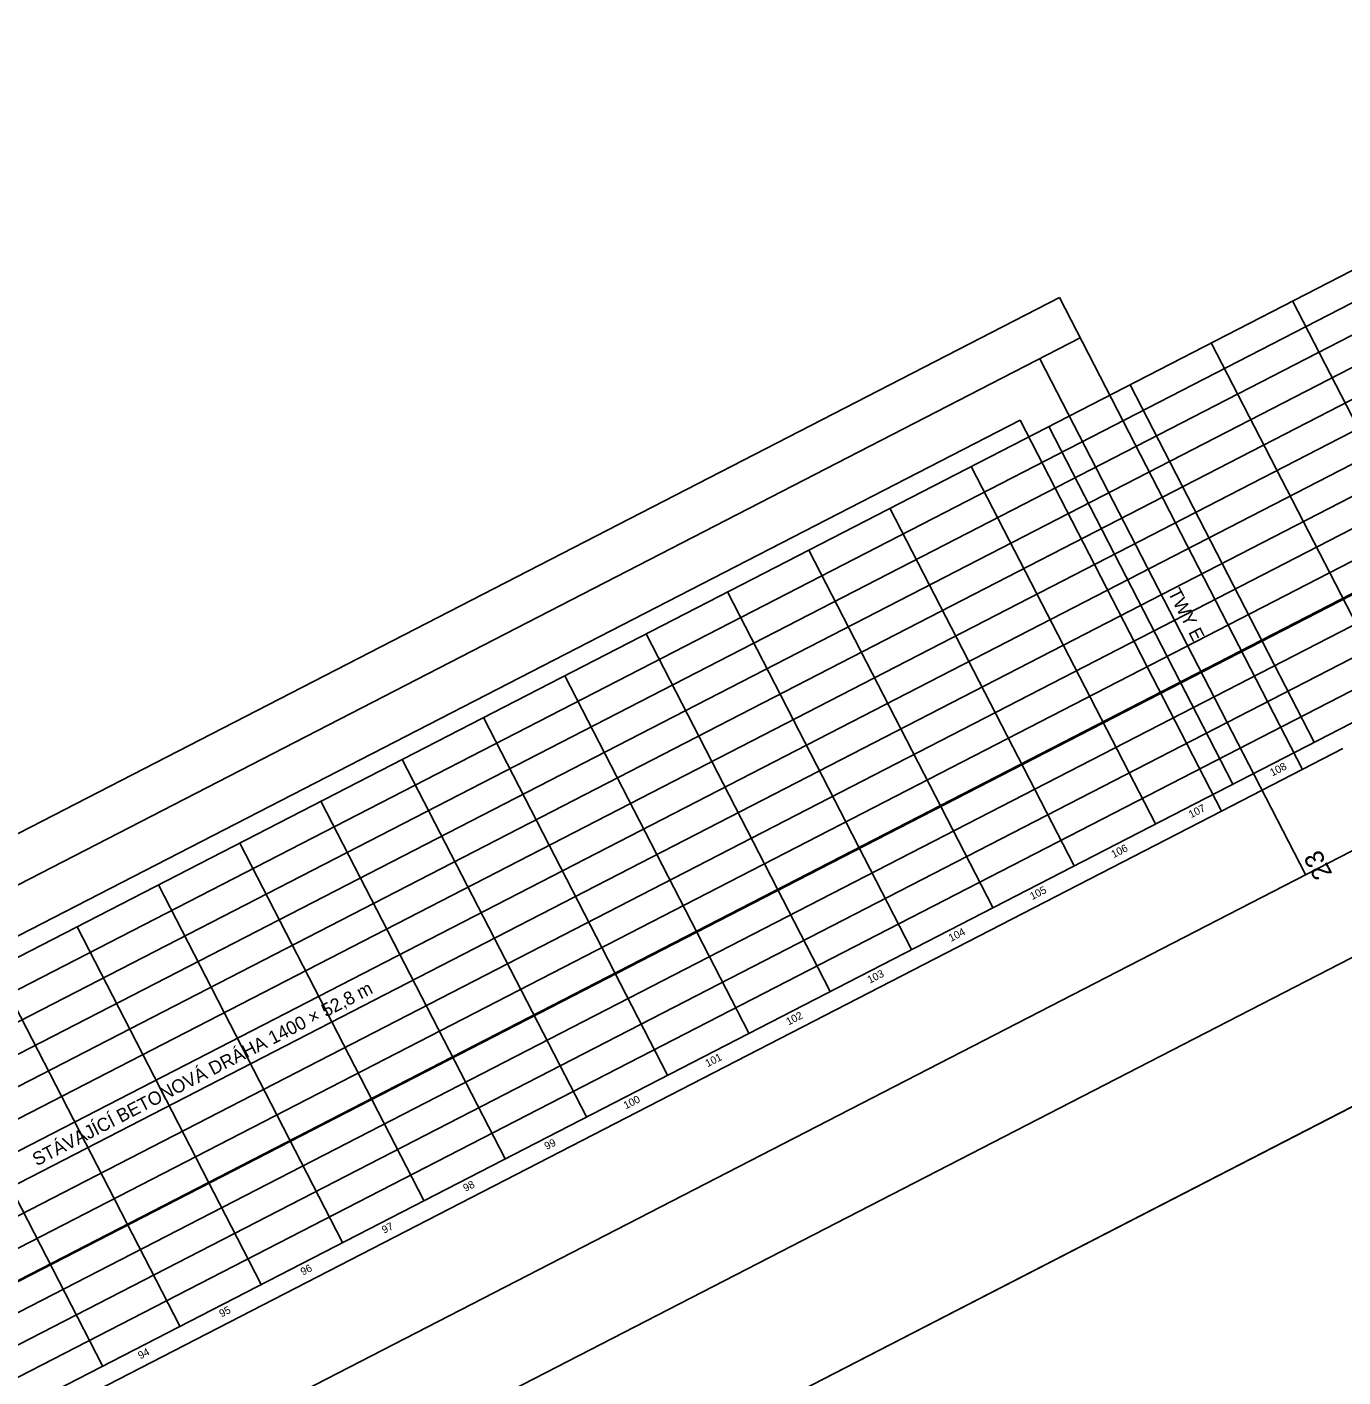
# Model space of a CAD drawing. Extents: x -886320 to -884760, y -1024172 to -1023483.
# Drawn here: x -885022 to -884848.5, y -1023661.3 to -1023483.3 of the extents above; entities that cross this region are included whole.
import ezdxf

# ---------------------------------------------------------------- set-up
doc = ezdxf.new("R2010")
doc.units = 0
for name, color, linetype in [('AGA__Netisknout', 7, 'Continuous'), ('Stavajici_betonova_draha', 7, 'Continuous'), ('Stavajici_betonova_draha_osa', 7, 'Continuous'), ('Stavajici_betonova_draha_popis', 7, 'Continuous'), ('Stavajici_betonova_draha_Popis desky', 7, 'Continuous'), ('Stavajici_betonova_draha_Spára', 7, 'Continuous'), ('Stavajici_drahovy_system', 7, 'Continuous'), ('Stavajici_drahovy_system_osy', 7, 'Continuous'), ('Stavajici_drahovy_system_popis', 7, 'Continuous'), ('Stavajici_drahovy_system_RWY_strip', 7, 'Continuous'), ('Stavajici_drahovy_system_TWY', 7, 'Continuous'), ('Stavajici_drahovy_system_TWY_osy', 7, 'Continuous'), ('Stavajici_drahovy_system_TWY_popis', 7, 'Continuous')]:
    doc.layers.add(name, color=color, linetype=linetype)

msp = doc.modelspace()

# ---------------------------------------------------------------- linework, layer by layer
at = {"layer": 'AGA__Netisknout'}
msp.add_line((-886017.78, -1024147.99), (-884773.13, -1023507.02), dxfattribs=at)
at = {"layer": 'Stavajici_betonova_draha'}
for p, q in [((-886029.69, -1024124.32), (-884785.04, -1023483.35)), ((-886029.69, -1024124.32), (-884785.04, -1023483.35)), ((-886005.42, -1024171.44), (-884760.77, -1023530.47)), ((-886005.42, -1024171.44), (-884760.77, -1023530.47))]:
    msp.add_line(p, q, dxfattribs=at)
at = {"layer": 'Stavajici_betonova_draha_osa'}
msp.add_line((-886017.55, -1024147.88), (-884772.9, -1023506.91), dxfattribs=at)
at = {"layer": 'Stavajici_betonova_draha_Spára'}
for p, q in [((-886029.91, -1024124.43), (-884785.26, -1023483.46)), ((-886028.18, -1024127.8), (-884783.53, -1023486.82)), ((-886026.44, -1024131.16), (-884781.79, -1023490.19)), ((-886024.71, -1024134.53), (-884780.06, -1023493.56)), ((-886022.98, -1024137.89), (-884778.33, -1023496.92)), ((-886021.24, -1024141.26), (-884776.59, -1023500.29)), ((-886019.51, -1024144.63), (-884774.86, -1023503.65)), ((-886016.04, -1024151.36), (-884771.39, -1023510.39)), ((-886014.31, -1024154.72), (-884769.66, -1023513.75)), ((-886012.58, -1024158.09), (-884767.93, -1023517.12)), ((-884855.17, -1023519.46), (-884830.91, -1023566.59)), ((-886010.84, -1024161.46), (-884766.19, -1023520.48)), ((-886009.11, -1024164.82), (-884764.46, -1023523.85)), ((-884865.89, -1023524.98), (-884841.62, -1023572.1)), ((-886007.38, -1024168.19), (-884762.73, -1023527.21)), ((-886005.64, -1024171.55), (-884760.99, -1023530.58)), ((-884876.6, -1023530.5), (-884852.33, -1023577.62)), ((-884887.31, -1023536.01), (-884863.05, -1023583.14)), ((-884897.53, -1023541.27), (-884873.26, -1023588.4)), ((-884908.24, -1023546.79), (-884883.97, -1023593.91)), ((-884918.95, -1023552.31), (-884894.69, -1023599.43)), ((-884929.67, -1023557.82), (-884905.4, -1023604.95)), ((-884940.38, -1023563.34), (-884916.11, -1023610.46)), ((-884951.09, -1023568.86), (-884926.82, -1023615.98)), ((-884961.8, -1023574.38), (-884937.54, -1023621.5)), ((-884972.52, -1023579.89), (-884948.25, -1023627.02)), ((-884983.23, -1023585.41), (-884958.96, -1023632.53)), ((-884993.94, -1023590.93), (-884969.68, -1023638.05)), ((-885004.66, -1023596.44), (-884980.39, -1023643.57)), ((-885015.37, -1023601.96), (-884991.1, -1023649.08)), ((-885026.08, -1023607.48), (-885001.81, -1023654.6)), ((-885036.26, -1023612.72), (-885012, -1023659.84))]:
    msp.add_line(p, q, dxfattribs=at)
at = {"layer": 'Stavajici_drahovy_system'}
for p, q in [((-884864.53, -1023586.71), (-884848.53, -1023578.47)), ((-885721.56, -1024028.07), (-884864.53, -1023586.71)), ((-885726.12, -1024058.54), (-884837.08, -1023600.7)), ((-885744.78, -1024087.83), (-884802.4, -1023602.52))]:
    msp.add_line(p, q, dxfattribs=at)
at = {"layer": 'Stavajici_drahovy_system_osy'}
msp.add_line((-885731.84, -1024047.42), (-884842.81, -1023589.59), dxfattribs=at)
at = {"layer": 'Stavajici_drahovy_system_RWY_strip'}
for p, q in [((-885772.25, -1024034.49), (-884829.87, -1023549.18)), ((-884802.4, -1023602.52), (-885744.78, -1024087.83))]:
    msp.add_line(p, q, dxfattribs=at)
at = {"layer": 'Stavajici_drahovy_system_TWY'}
for p, q in [((-885887.27, -1024034.67), (-884885.91, -1023518.99)), ((-884853.86, -1023581.22), (-884885.91, -1023518.99)), ((-885748.12, -1023976.51), (-884891.09, -1023535.15)), ((-884864.53, -1023586.71), (-884891.09, -1023535.15))]:
    msp.add_line(p, q, dxfattribs=at)
at = {"layer": 'Stavajici_drahovy_system_TWY_osy'}
for p, q in [((-885886.7, -1024041.13), (-884883.17, -1023524.32)), ((-884853.47, -1023595.08), (-884888.5, -1023527.07))]:
    msp.add_line(p, q, dxfattribs=at)

# ---------------------------------------------------------------- texts
at = {"layer": 'Stavajici_betonova_draha_popis'}
msp.add_text('STÁVAJÍCÍ BETONOVÁ DRÁHA 1400 × 52,8 m', height=1.75, rotation=27.2477, dxfattribs=at).set_placement((-885020.69, -1023633.53))
at = {"layer": 'Stavajici_betonova_draha_Popis desky'}
for s, p in [('108', (-884857.84, -1023582.14)), ('107', (-884868.55, -1023587.66)), ('106', (-884878.76, -1023592.92)), ('105', (-884889.48, -1023598.44)), ('104', (-884900.19, -1023603.95)), ('103', (-884910.9, -1023609.47)), ('102', (-884921.61, -1023614.98)), ('101', (-884932.26, -1023620.47)), ('100', (-884943.04, -1023626.02)), ('99', (-884953.47, -1023631.39)), ('98', (-884964.18, -1023636.91)), ('97', (-884974.9, -1023642.42)), ('96', (-884985.61, -1023647.94)), ('95', (-884996.33, -1023653.46)), ('94', (-885007.03, -1023658.98))]:
    msp.add_text(s, height=1, rotation=27.2477, dxfattribs=at).set_placement(p)
at = {"layer": 'Stavajici_drahovy_system_popis'}
msp.add_text('23', height=2.5, rotation=117.2477, dxfattribs=at).set_placement((-884849.89, -1023594.95))
at = {"layer": 'Stavajici_drahovy_system_TWY_popis'}
msp.add_text('TWY E', height=1.75, rotation=297.2477, dxfattribs=at).set_placement((-884871.64, -1023557.9))

doc.saveas('drawing.dxf')
